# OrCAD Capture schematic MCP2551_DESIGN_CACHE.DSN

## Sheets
1 03_POWER AND CONNECTORS: size A; title: Window Circuit; rev: A; company: EMA Design Automation; note: EMA-12345678; note: 225 Tech Park Dr; note: Rochester, NY, 14623
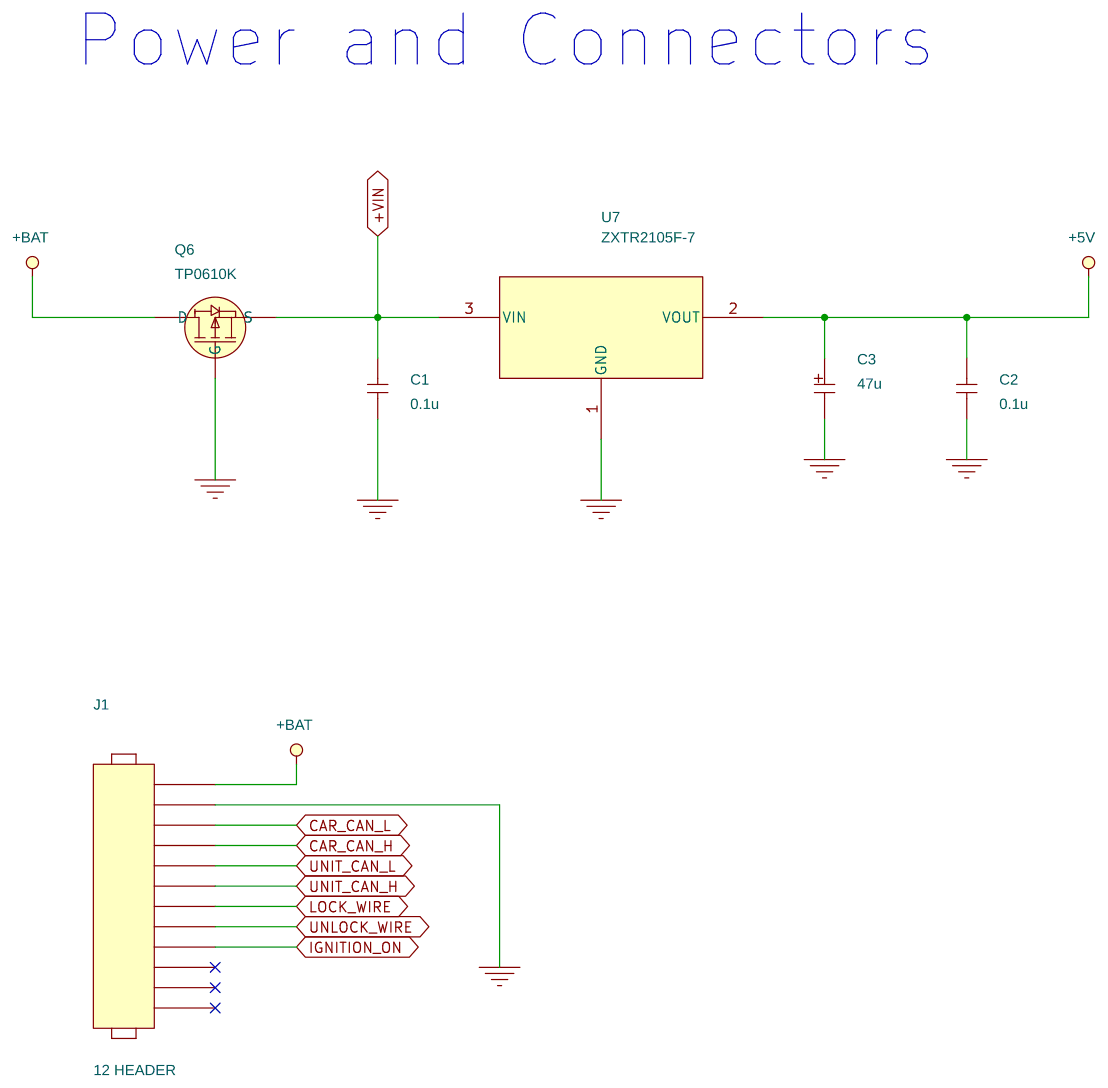
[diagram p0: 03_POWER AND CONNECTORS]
2 04_PROCESSING: size A
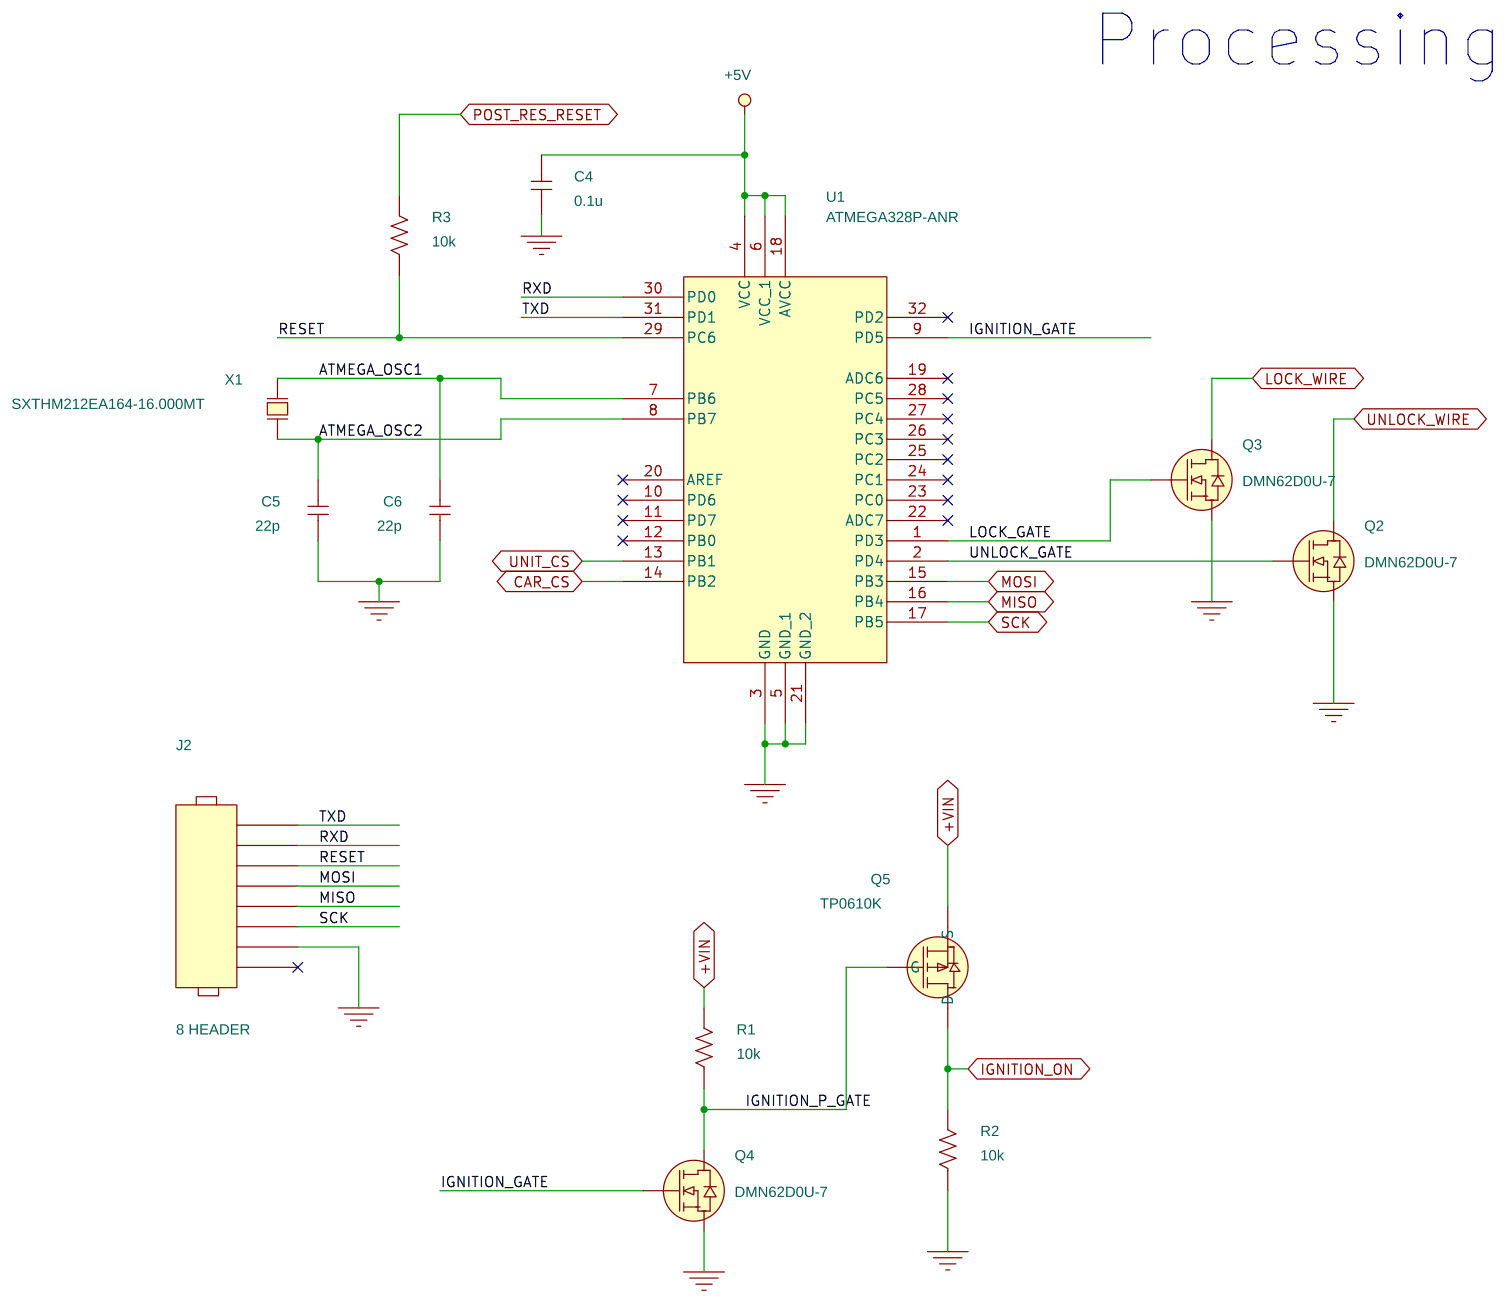
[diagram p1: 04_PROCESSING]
3 05_CAN TRANCEIVERS: size A
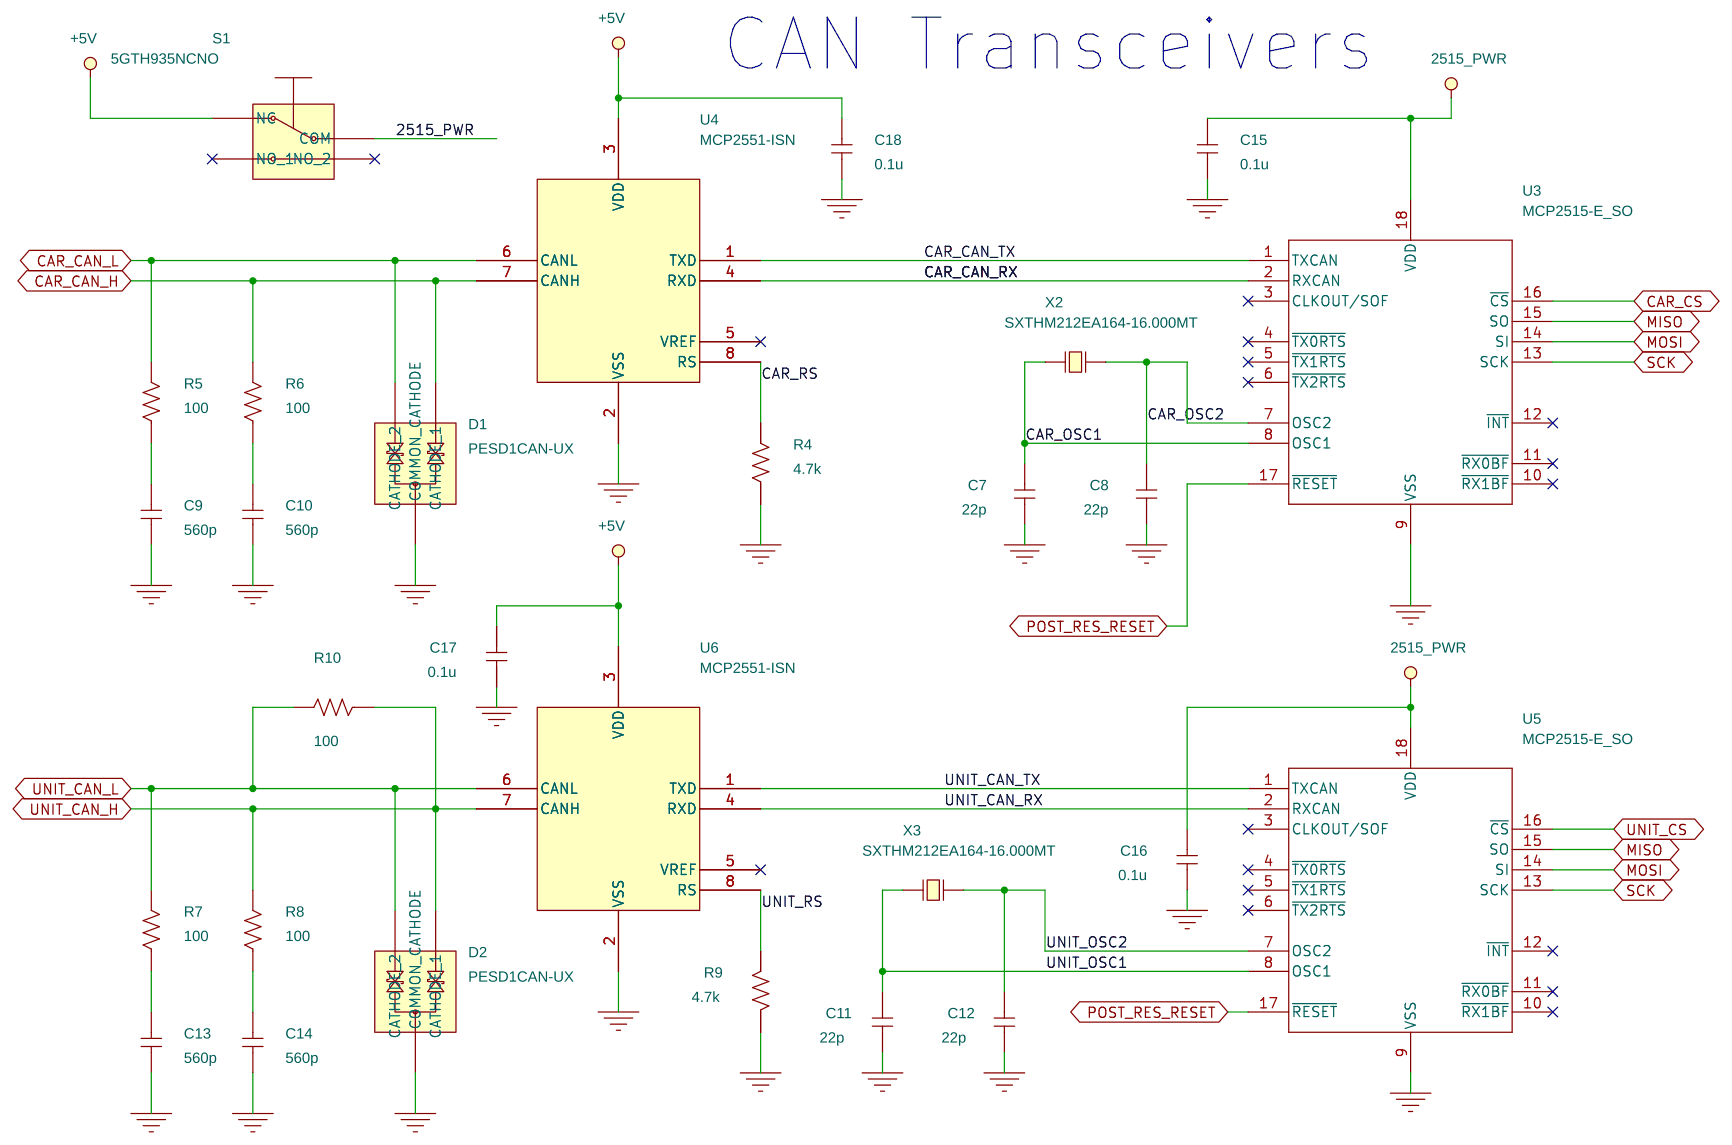
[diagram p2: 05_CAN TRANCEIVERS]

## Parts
sheet 03_POWER AND CONNECTORS
C1  0.1u  [0603_AVX]
C2  0.1u  [0603_AVX]
C3  47u  [CAP_MH5_6P3X5_RUB]
J1  12 HEADER  [CON_532541270_MOL]
Q6  TP0610K  [SOT-23_TP01]
U7  ZXTR2105F-7  [SOT23_DIO]
sheet 04_PROCESSING
C4  0.1u  [0603_AVX]
C5  22p  [0603_AVX]
C6  22p  [0603_AVX]
J2  8 HEADER  [CONN_90131-0764_MOL]
Q2  DMN62D0U-7  [PG-SOT23-3-5_INF_MIN]
Q3  DMN62D0U-7  [PG-SOT23-3-5_INF_MIN]
Q4  DMN62D0U-7  [PG-SOT23-3-5_INF_MIN]
Q5  TP0610K  [SOT-23_TP01]
R1  10k  [0603_AVX]
R2  10k  [0603_AVX]
R3  10k  [0603_AVX]
U1  ATMEGA328P-ANR  [32A_ATM]
X1  SXTHM212EA164-16.000MT  [ABLS-8P000MHZ-B2-T_ABR-L]
sheet 05_CAN TRANCEIVERS
C7  22p  [0603_AVX]
C8  22p  [0603_AVX]
C9  560p  [0603_AVX]
C10  560p  [0603_AVX]
C11  22p  [0603_AVX]
C12  22p  [0603_AVX]
C13  560p  [0603_AVX]
C14  560p  [0603_AVX]
C15  0.1u  [0603_AVX]
C16  0.1u  [0603_AVX]
C17  0.1u  [0603_AVX]
C18  0.1u  [0603_AVX]
D1  PESD1CAN-UX  [SOT23_NEX]
D2  PESD1CAN-UX  [SOT23_NEX]
R4  4.7k  [0603_AVX]
R5  100  [0603_AVX]
R6  100  [0603_AVX]
R7  100  [0603_AVX]
R8  100  [0603_AVX]
R9  4.7k  [0603_AVX]
R10  100  [0603_AVX]
S1  5GTH935NCNO  [5GTH935NCNO]
U3  MCP2515-E_SO  [SOIC18-W_MC_MCH]
U4  MCP2551-ISN  [SOIC8-N_MC_MCH]
U5  MCP2515-E_SO  [SOIC18-W_MC_MCH]
U6  MCP2551-ISN  [SOIC8-N_MC_MCH]
X2  SXTHM212EA164-16.000MT  [ABLS-8P000MHZ-B2-T_ABR-L]
X3  SXTHM212EA164-16.000MT  [ABLS-8P000MHZ-B2-T_ABR-L]

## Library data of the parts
C1 C2 = C: ROOM: POWER; Supplier: DigiKey; Supplier_PN: 1276-1935-1-ND
C3 = C_elect: ROOM: POWER; Supplier: DigiKey; Supplier_PN: 1189-2912-ND
J1 = 12_HEADER: ROOM: POWER; Supplier: DigiKey; Supplier_PN: WM12268-ND
Q6 = TP0610K-T1-E3_1: MOSFET P-CH 60V 185MA SOT23-3; Category: Transistors - FETs, MOSFETs - Single; Distributor: Digi-Key; Distributor_PN: TP0610K-T1-E3TR-ND; MPN: TP0610K-T1-E3; Manufacturer: Vishay; Mounting_Type: Surface Mount; Operating_Temperature: -55掳C ~ 150掳C (TJ); Package_Case: TO-236-3, SC-59, SOT-23-3; Package_Category: Tape & Reel (TR); ROHS: false; ROOM: POWER; Series: TrenchFET庐; Status: Active; Supplier: DigiKey; Supplier_Device_Package: SOT-23-3 (TO-236); Supplier_PN: TP0610K-T1-E3CT-ND
U7 = ZXTR2105F-7_1: IC REG LINEAR 5V 89MA SOT23; Category: PMIC - Voltage Regulators - Linear; Distributor: Digi-Key; Distributor_PN: ZXTR2105F-7DITR-ND; Manufacturer: Diodes Inc; Mounting_Type: Surface Mount; Operating_Temperature: -65掳C ~ 150掳C; Package_Case: TO-236-3, SC-59, SOT-23-3; Package_Category: Tape & Reel (TR); ROHS: false; ROOM: POWER; Series: Automotive, AEC-Q101; Status: Active; Supplier: DigiKey; Supplier_Device_Package: SOT-23-3; Supplier_PN: ZXTR2105F-7DICT-ND
C4 = C: ROOM: PROCESSING; Supplier: DigiKey; Supplier_PN: 1276-1935-1-ND
C5 C6 = C: ROOM: PROCESSING; Supplier: DigiKey; Supplier_PN: 1292-1503-1-ND
J2 = 8_HEADER: ROOM: PROGRAMMING; Supplier: DigiKey; Supplier_PN: WM8140-ND
Q2-Q4 = 2N7002H6327XTSA2_0: MOSFET N-CH 60V 300MA SOT23-3; Category: Home MOSFET; Distributor: Digi-Key; Distributor_PN: 2N7002H6327XTSA2TR-ND; MPN: 2N7002H6327XTSA2; Manufacturer: Infineon; Mounting_Type: Surface Mount; Operating_Temperature: -55掳C ~ 150掳C (TJ); Package_Case: TO-236-3, SC-59, SOT-23-3; Package_Category: Tape & Reel (TR); ROHS: false; ROOM: PROCESSING; Series: OptiMOSâ„¢; Status: Active; Supplier: DigiKey; Supplier_Device_Package: PG-SOT23; Supplier_PN: DMN62D0U-7DICT-ND
Q5 = TP0610K-T1-E3_1: MOSFET P-CH 60V 185MA SOT23-3; Category: Transistors - FETs, MOSFETs - Single; Distributor: Digi-Key; Distributor_PN: TP0610K-T1-E3TR-ND; MPN: TP0610K-T1-E3; Manufacturer: Vishay; Mounting_Type: Surface Mount; Operating_Temperature: -55掳C ~ 150掳C (TJ); Package_Case: TO-236-3, SC-59, SOT-23-3; Package_Category: Tape & Reel (TR); ROHS: false; ROOM: PROCESSING; Series: TrenchFET庐; Status: Active; Supplier: DigiKey; Supplier_Device_Package: SOT-23-3 (TO-236); Supplier_PN: TP0610K-T1-E3CT-ND
R1-R3 = R: ROOM: PROCESSING; Supplier: DigiKey; Supplier_PN: RNCP0603FTD10K0CT-ND
U1 = ATMEGA328P-ANR_6: IC MCU 8BIT 32KB FLASH 32TQFP; Category: Embedded - Microcontrollers; Distributor: Digi-Key; Distributor_PN: ATMEGA328P-ANRTR-ND; Manufacturer: Microchip; Mounting_Type: Surface Mount; Operating_Temperature: -40掳C ~ 105掳C (TA); Package_Case: 32-TQFP; Package_Category: Tape & Reel (TR); ROHS: false; ROOM: PROCESSING; Series: AVR庐 ATmega; Status: Active; Supplier: DigiKey; Supplier_Device_Package: 32-TQFP (7x7); Supplier_PN: ATMEGA328P-AN-ND
X1 = SXTHM212EA164-16_1.000MT: ROOM: PROCESSING; Supplier: DigiKey; Supplier_PN: 2388-SXTHM212EA164-16.000M-ND
C7 C8 C11 C12 = C: ROOM: TRANSCEIVER; Supplier: DigiKey; Supplier_PN: 1292-1503-1-ND
C9 C10 C13 C14 = C: ROOM: TRANSCEIVER; Supplier: DigiKey; Supplier_PN: 478-5002-1-ND
C15-C18 = C: ROOM: TRANSCEIVER; Supplier: DigiKey; Supplier_PN: 1276-1935-1-ND
D1 D2 = PESD1CAN-UX_0: 3D_Image_URL: https://componentsearchengine.com/2D/0/1022121.png; Body_Length: 2.2; Body_Width: 1.35; Category: Diode; Confidence: C2 - Manufacturer collaboration; Height: 1.1; Manufacturer: Nexperia; Package_Category: SOT23 (3-Pin); Pin_Count: 3; ROOM: TRANSCEIVER; Released_Date: 2018-05-24 12:30:54; Source_Version: 3.1; Status: Released; Supplier: DigiKey; Supplier_PN: 1727-1306-1-ND
R4 R9 = R: ROOM: TRANSCEIVER; Supplier: DigiKey; Supplier_PN: 1292-WR06X472JTLCT-ND
R5-R8 = R: ROOM: TRANSCEIVER; Supplier: DigiKey; Supplier_PN: A130404CT-ND
R10 = R: NO_XNET_CONNECTION: 1; ROOM: TRANSCEIVER; Supplier: DigiKey; Supplier_PN: A130404CT-ND
S1 = 5GTH935NCNO_0: Tactile Switches 50mA 24VDC 3.5N NCNO TH IP67 High performance tactile switches â€¢ MIL-PRF-28855H â€¢ excellent illumination; 3D_Image_URL: https://componentsearchengine.com/2D/0T/623757.1.6.png; Body_Length: 0; Body_Width: 0; Category: Switch; Confidence: C0 - Untested community built part; Height: 6.6; Manufacturer: Apem; Package_Category: Other; Pin_Count: 4; ROOM: PROGRAMMING; Released_Date: 2021-04-01 19:52:29; Source_Version: 1.6; Status: Released; Supplier_PN: 679-3571-ND
U3 U5 = MCP2515-E_SO_0: 3D_Image_URL: https://componentsearchengine.com/2D/0T/159067.4.1.png; Body_Length: 11.55; Body_Width: 7.5; Category: Integrated Circuit; Confidence: C3 - Community checked; Height: 2.65; MPN: MCP2515-E/SO; Manufacturer: Microchip; Package_Category: Small Outline Packages; Pin_Count: 18; ROOM: TRANSCEIVER; Released_Date: 2015-04-16 09:48:08; Source_Version: 4.1; Status: Released; Supplier: DigiKey; Supplier_PN: MCP2515T-I/SOCT-ND
U4 U6 = MCP2551-ISN_0: IC TRANSCEIVER HALF 1/1 8SOIC; Category: Interface - Drivers, Receivers, Transceivers; Distributor: Digi-Key; Distributor_PN: MCP2551-I/SN-ND; MPN: MCP2551-I/SN; Manufacturer: Microchip; Mounting_Type: Surface Mount; Operating_Temperature: -40掳C ~ 85掳C; Package_Case: 8-SOIC (0.154", 3.90mm Width); Package_Category: Tube; ROHS: false; ROOM: TRANSCEIVER; Status: Active; Supplier: DigiKey; Supplier_Device_Package: 8-SOIC; Supplier_PN: MCP2551-I/SN-ND; Type: Transceiver; Voltage_Supply: 4.5V ~ 5.5V
X2 X3 = SXTHM212EA164-16_1.000MT: ROOM: TRANSCEIVER; Supplier: DigiKey; Supplier_PN: 2388-SXTHM212EA164-16.000M-ND

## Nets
+5V: C2.2 C3.P(+) C4.2 C17.2 C18.2 S1.1(NC) U1.4(VCC) U1.6(VCC_1) U1.18(AVCC) U4.3(VDD) U6.3(VDD) U7.2(VOUT)
+VIN: C1.2 Q5.2(S) Q6.2(S) R1.2 U7.3(VIN)
0: C1.1 C2.1 C3.N(-) C4.1 C5.1 C6.1 C7.1 C8.1 C9.1 C10.1 C11.1 C12.1 C13.1 C14.1 C15.1 C16.1 C17.1 C18.1 D1.3(COMMON_CATHODE) D2.3(COMMON_CATHODE) J1.2 J2.7 Q2.2 Q3.2 Q4.2 Q6.1(G) R2.1 R4.1 R9.1 U1.3(GND) U1.5(GND_1) U1.21(GND_2) U3.9(VSS) U4.2(VSS) U5.9(VSS) U6.2(VSS) U7.1(GND)
2515_PWR: C15.2 C16.2 S1.2(COM) U3.18(VDD) U5.18(VDD)
+BAT: J1.1 Q6.3(D)
ATMEGA_OSC1: C6.2 U1.7(PB6) X1.1(X1)
ATMEGA_OSC2: C5.2 U1.8(PB7) X1.2(X2)
CAR_CAN_H: D1.1(CATHODE) J1.4 R6.2 U4.7(CANH)
CAR_CAN_L: D1.2(CATHODE) J1.3 R5.2 U4.6(CANL)
CAR_CAN_RX: U3.2(RXCAN) U4.4(RXD)
CAR_CAN_TX: U3.1(TXCAN) U4.1(TXD)
CAR_CS: U1.14(PB2) U3.16(~{CS})
CAR_OSC1: C7.2 U3.8(OSC1) X2.1(X1)
CAR_OSC2: C8.2 U3.7(OSC2) X2.2(X2)
CAR_RS: R4.2 U4.8(RS)
IGNITION_GATE: Q4.1 U1.9(PD5)
IGNITION_ON: J1.9 Q5.3(D) R2.2
IGNITION_P_GATE: Q4.3 Q5.1(G) R1.1
LOCK_GATE: Q3.1 U1.1(PD3)
LOCK_WIRE: J1.7 Q3.3
MISO: J2.5 U1.16(PB4) U3.15(SO) U5.15(SO)
MOSI: J2.4 U1.15(PB3) U3.14(SI) U5.14(SI)
POST_RES_RESET: R3.2 U3.17(~{RESET}) U5.17(~{RESET})
RESET: J2.3 R3.1 U1.29(PC6)
RXD: J2.2 U1.30(PD0)
SCK: J2.6 U1.17(PB5) U3.13(SCK) U5.13(SCK)
TXD: J2.1 U1.31(PD1)
UNIT_CAN_H: D2.1(CATHODE) J1.6 R8.2 R10.1 U6.7(CANH)
UNIT_CAN_L: D2.2(CATHODE) J1.5 R7.2 R10.2 U6.6(CANL)
UNIT_CAN_RX: U5.2(RXCAN) U6.4(RXD)
UNIT_CAN_TX: U5.1(TXCAN) U6.1(TXD)
UNIT_CS: U1.13(PB1) U5.16(~{CS})
UNIT_OSC1: C11.2 U5.8(OSC1) X3.1(X1)
UNIT_OSC2: C12.2 U5.7(OSC2) X3.2(X2)
UNIT_RS: R9.2 U6.8(RS)
UNLOCK_GATE: Q2.1 U1.2(PD4)
UNLOCK_WIRE: J1.8 Q2.3
N11183: C9.2 R5.1
N11215: C10.2 R6.1
N13031: C13.2 R7.1
N13035: C14.2 R8.1

Not connected (* = marked no-connect by the designer): J1 10* 11* 12*; J2 8*; S1 3(NO_1)* 4(NO_2)*; U1 10(PD6)* 11(PD7)* 12(PB0)* 19(ADC6)* 20(AREF)* 22(ADC7)* 23(PC0)* 24(PC1)* 25(PC2)* 26(PC3)* 27(PC4)* 28(PC5)* 32(PD2)*; U3 3(CLKOUT/SOF)* 4(~{TX0RTS})* 5(~{TX1RTS})* 6(~{TX2RTS})* 10(~{RX1BF})* 11(~{RX0BF})* 12(~{INT})*; U4 5(VREF)*; U5 3(CLKOUT/SOF)* 4(~{TX0RTS})* 5(~{TX1RTS})* 6(~{TX2RTS})* 10(~{RX1BF})* 11(~{RX0BF})* 12(~{INT})*; U6 5(VREF)*

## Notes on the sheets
sheet 1
- Power and Connectors
sheet 2
- Processing
sheet 3
- CAN Transceivers
